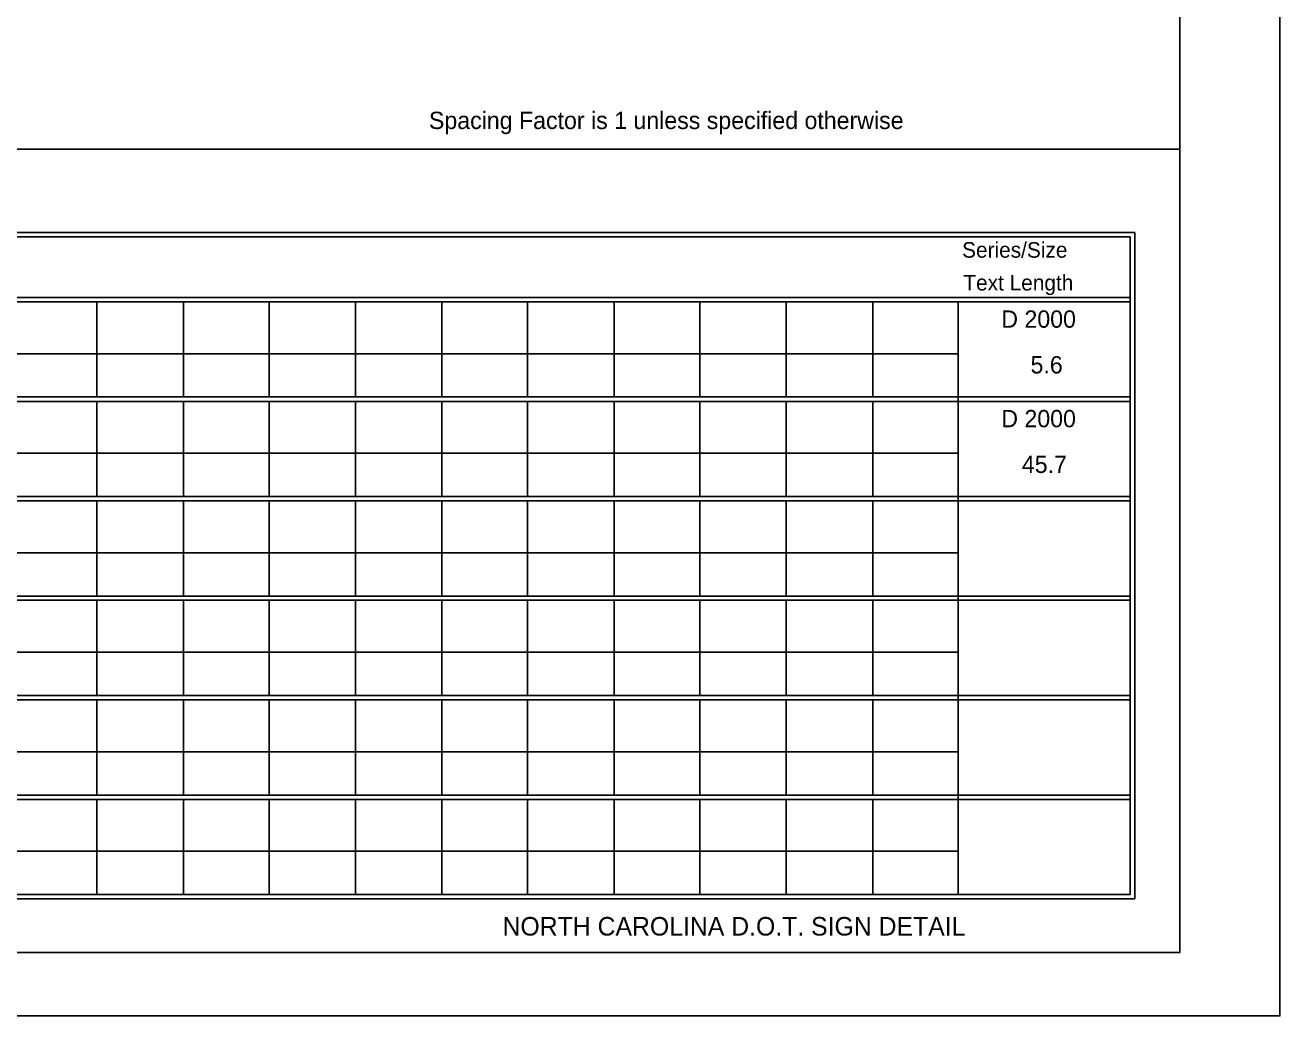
# Model space of a CAD drawing. Extents: x 1708.4 to 1771.6, y 238.3 to 283.4.
# Drawn here: x 1725.12 to 1738.44, y 238.25 to 248.77 of the extents above; entities that cross this region are included whole.
import ezdxf

# ---------------------------------------------------------------- set-up
doc = ezdxf.new("R2010")
doc.units = 0
doc.layers.add('Level 6', color=7, linetype='Continuous')
doc.layers.add('Level 9', color=7, linetype='Continuous')

msp = doc.modelspace()

# ---------------------------------------------------------------- linework, layer by layer
at = {"layer": 'Level 6'}
for p, q in [((1720.221, 247.448), (1737.376, 247.448)), ((1709.428, 245.876), (1731.195, 245.876)), ((1709.428, 245.83), (1731.195, 245.83)), ((1725.883, 245.83), (1725.883, 244.82)), ((1726.8, 245.83), (1726.8, 244.82)), ((1727.709, 245.83), (1727.709, 244.82)), ((1728.627, 245.83), (1728.627, 244.82)), ((1729.544, 245.83), (1729.544, 244.82)), ((1730.221, 245.876), (1736.849, 245.876)), ((1730.221, 245.83), (1736.849, 245.83)), ((1730.453, 245.83), (1730.453, 244.82)), ((1730.453, 245.83), (1730.453, 244.82)), ((1731.371, 245.83), (1731.371, 244.82)), ((1732.279, 245.83), (1732.279, 244.82)), ((1733.197, 245.83), (1733.197, 244.82)), ((1734.115, 245.83), (1734.115, 244.82)), ((1735.023, 245.83), (1735.023, 239.61)), ((1710.346, 245.279), (1731.195, 245.279)), ((1730.221, 245.279), (1735.023, 245.279)), ((1735.023, 245.07), (1735.023, 244.82)), ((1709.428, 244.82), (1731.195, 244.82)), ((1709.428, 244.774), (1731.195, 244.774)), ((1725.883, 244.774), (1725.883, 243.764)), ((1726.8, 244.774), (1726.8, 243.764)), ((1727.709, 244.774), (1727.709, 243.764)), ((1728.627, 244.774), (1728.627, 243.764)), ((1729.544, 244.774), (1729.544, 243.764)), ((1730.221, 244.82), (1736.849, 244.82)), ((1730.221, 244.774), (1736.849, 244.774)), ((1730.453, 244.774), (1730.453, 243.764)), ((1730.453, 244.774), (1730.453, 243.764)), ((1731.371, 244.774), (1731.371, 243.764)), ((1732.279, 244.774), (1732.279, 243.764)), ((1733.197, 244.774), (1733.197, 243.764)), ((1734.115, 244.774), (1734.115, 243.764)), ((1735.023, 244.774), (1735.023, 244.295)), ((1710.346, 244.223), (1731.195, 244.223)), ((1730.221, 244.223), (1735.023, 244.223)), ((1735.023, 244.093), (1735.023, 243.764)), ((1709.428, 243.764), (1731.195, 243.764)), ((1709.428, 243.718), (1731.195, 243.718)), ((1725.883, 243.718), (1725.883, 242.708)), ((1726.8, 243.718), (1726.8, 242.708)), ((1727.709, 243.718), (1727.709, 242.708)), ((1728.627, 243.718), (1728.627, 242.708)), ((1729.544, 243.718), (1729.544, 242.708)), ((1730.221, 243.764), (1736.849, 243.764)), ((1730.221, 243.718), (1736.849, 243.718)), ((1730.453, 243.718), (1730.453, 242.708)), ((1730.453, 243.718), (1730.453, 242.708)), ((1731.371, 243.718), (1731.371, 242.708)), ((1732.279, 243.718), (1732.279, 242.708)), ((1733.197, 243.718), (1733.197, 242.708)), ((1734.115, 243.718), (1734.115, 242.708)), ((1735.023, 243.718), (1735.023, 243.308)), ((1710.346, 243.168), (1731.195, 243.168)), ((1730.221, 243.168), (1735.023, 243.168)), ((1735.023, 243.006), (1735.023, 242.708)), ((1709.428, 242.708), (1731.195, 242.708)), ((1709.428, 242.663), (1731.195, 242.663)), ((1725.883, 242.663), (1725.883, 241.653)), ((1726.8, 242.663), (1726.8, 241.653)), ((1727.709, 242.663), (1727.709, 241.653)), ((1728.627, 242.663), (1728.627, 241.653)), ((1729.544, 242.663), (1729.544, 241.653)), ((1730.221, 242.708), (1736.849, 242.708)), ((1730.221, 242.663), (1736.849, 242.663)), ((1730.453, 242.663), (1730.453, 241.653)), ((1730.453, 242.663), (1730.453, 241.653)), ((1731.371, 242.663), (1731.371, 241.653)), ((1732.279, 242.663), (1732.279, 241.653)), ((1733.197, 242.663), (1733.197, 241.653)), ((1734.115, 242.663), (1734.115, 241.653)), ((1735.023, 242.663), (1735.023, 242.22)), ((1710.346, 242.112), (1731.195, 242.112)), ((1730.221, 242.112), (1735.023, 242.112)), ((1735.023, 241.918), (1735.023, 241.653)), ((1725.883, 241.77), (1725.883, 241.653)), ((1726.8, 241.77), (1726.8, 241.653)), ((1727.709, 241.77), (1727.709, 241.653)), ((1728.627, 241.77), (1728.627, 241.653)), ((1729.544, 241.77), (1729.544, 241.653)), ((1730.453, 241.77), (1730.453, 241.653)), ((1730.453, 241.77), (1730.453, 241.653)), ((1731.371, 241.77), (1731.371, 241.653)), ((1732.279, 241.77), (1732.279, 241.653)), ((1733.197, 241.77), (1733.197, 241.653)), ((1734.115, 241.77), (1734.115, 241.653)), ((1735.023, 241.77), (1735.023, 241.653)), ((1709.428, 241.653), (1731.195, 241.653)), ((1709.428, 241.653), (1731.195, 241.653)), ((1709.428, 241.607), (1731.195, 241.607)), ((1709.428, 241.607), (1731.195, 241.607)), ((1725.883, 241.607), (1725.883, 240.663)), ((1725.883, 241.607), (1725.883, 240.597)), ((1726.8, 241.607), (1726.8, 240.663)), ((1726.8, 241.607), (1726.8, 240.597)), ((1727.709, 241.607), (1727.709, 240.663)), ((1727.709, 241.607), (1727.709, 240.597)), ((1728.627, 241.607), (1728.627, 240.663)), ((1728.627, 241.607), (1728.627, 240.597)), ((1729.544, 241.607), (1729.544, 240.663)), ((1729.544, 241.607), (1729.544, 240.597)), ((1730.221, 241.653), (1736.849, 241.653)), ((1730.221, 241.653), (1736.849, 241.653)), ((1730.221, 241.607), (1736.849, 241.607)), ((1730.221, 241.607), (1736.849, 241.607)), ((1730.453, 241.607), (1730.453, 240.663)), ((1730.453, 241.607), (1730.453, 240.597)), ((1730.453, 241.607), (1730.453, 240.663)), ((1730.453, 241.607), (1730.453, 240.597)), ((1731.371, 241.607), (1731.371, 240.663)), ((1731.371, 241.607), (1731.371, 240.597)), ((1732.279, 241.607), (1732.279, 240.663)), ((1732.279, 241.607), (1732.279, 240.597)), ((1733.197, 241.607), (1733.197, 240.663)), ((1733.197, 241.607), (1733.197, 240.597)), ((1734.115, 241.607), (1734.115, 240.663)), ((1734.115, 241.607), (1734.115, 240.597)), ((1735.023, 241.607), (1735.023, 241.152)), ((1735.023, 241.607), (1735.023, 241.152)), ((1710.346, 241.056), (1731.195, 241.056)), ((1710.346, 241.056), (1731.195, 241.056)), ((1730.221, 241.056), (1735.023, 241.056)), ((1730.221, 241.056), (1734.785, 241.056)), ((1735.023, 240.89), (1735.023, 240.663)), ((1735.023, 240.89), (1735.023, 240.597)), ((1725.883, 240.714), (1725.883, 240.597)), ((1726.8, 240.714), (1726.8, 240.597)), ((1727.709, 240.714), (1727.709, 240.597)), ((1728.627, 240.714), (1728.627, 240.597)), ((1729.544, 240.714), (1729.544, 240.597)), ((1730.453, 240.714), (1730.453, 240.597)), ((1730.453, 240.714), (1730.453, 240.597)), ((1731.371, 240.714), (1731.371, 240.597)), ((1732.279, 240.714), (1732.279, 240.597)), ((1733.197, 240.714), (1733.197, 240.597)), ((1734.115, 240.714), (1734.115, 240.597)), ((1735.023, 240.714), (1735.023, 240.597)), ((1709.428, 240.597), (1731.195, 240.597)), ((1709.428, 240.597), (1731.195, 240.597)), ((1709.428, 240.551), (1731.195, 240.551)), ((1709.428, 240.551), (1731.195, 240.551)), ((1725.883, 240.551), (1725.883, 239.541)), ((1725.883, 240.551), (1725.883, 239.541)), ((1726.8, 240.551), (1726.8, 239.541)), ((1726.8, 240.551), (1726.8, 239.541)), ((1727.709, 240.551), (1727.709, 239.541)), ((1727.709, 240.551), (1727.709, 239.541)), ((1728.627, 240.551), (1728.627, 239.541)), ((1728.627, 240.551), (1728.627, 239.541)), ((1729.544, 240.551), (1729.544, 239.541)), ((1729.544, 240.551), (1729.544, 239.541)), ((1730.221, 240.597), (1736.849, 240.597)), ((1730.221, 240.597), (1736.849, 240.597)), ((1730.221, 240.551), (1736.849, 240.551)), ((1730.221, 240.551), (1736.849, 240.551)), ((1730.453, 240.551), (1730.453, 239.541)), ((1730.453, 240.551), (1730.453, 239.541)), ((1730.453, 240.551), (1730.453, 239.541)), ((1730.453, 240.551), (1730.453, 239.541)), ((1731.371, 240.551), (1731.371, 239.541)), ((1731.371, 240.551), (1731.371, 239.541)), ((1732.279, 240.551), (1732.279, 239.541)), ((1732.279, 240.551), (1732.279, 239.541)), ((1733.197, 240.551), (1733.197, 239.541)), ((1733.197, 240.551), (1733.197, 239.541)), ((1734.115, 240.551), (1734.115, 239.541)), ((1734.115, 240.551), (1734.115, 239.541)), ((1735.023, 240.551), (1735.023, 240.126)), ((1735.023, 240.551), (1735.023, 240.126)), ((1710.346, 240), (1731.195, 240)), ((1710.346, 240), (1731.195, 240)), ((1730.221, 240), (1735.023, 240)), ((1730.221, 240), (1734.847, 240)), ((1735.023, 239.803), (1735.023, 239.541)), ((1735.023, 239.803), (1735.023, 239.541)), ((1709.381, 239.495), (1731.195, 239.495)), ((1709.428, 239.541), (1731.195, 239.541)), ((1709.428, 239.541), (1731.195, 239.541)), ((1709.428, 239.495), (1731.195, 239.495)), ((1730.221, 239.541), (1736.849, 239.541)), ((1730.221, 239.541), (1736.849, 239.541)), ((1730.221, 239.495), (1736.896, 239.495)), ((1730.221, 239.495), (1736.849, 239.495))]:
    msp.add_line(p, q, dxfattribs=at)
msp.add_lwpolyline([(1709.065, 258.583), (1737.376, 258.583), (1737.376, 238.927), (1709.065, 238.927)], close=True, dxfattribs=at)
for points in [[(1709.381, 240.663), (1709.381, 246.565), (1731.195, 246.565)], [(1709.428, 240.663), (1709.428, 246.519), (1731.195, 246.519)], [(1730.221, 246.565), (1736.896, 246.565), (1736.896, 240.663)], [(1730.221, 246.519), (1736.849, 246.519), (1736.849, 240.663)], [(1736.849, 241.77), (1736.849, 239.541)], [(1736.896, 241.77), (1736.896, 239.495)]]:
    msp.add_lwpolyline(points, dxfattribs=at)
at = {"layer": 'Level 9'}
msp.add_lwpolyline([(1708.374, 238.254), (1738.436, 238.254), (1738.436, 259.278), (1708.374, 259.278)], close=True, dxfattribs=at)

# ---------------------------------------------------------------- texts
at = {"layer": 'Level 6'}
for s, height, p in [('Spacing Factor is 1 unless specified otherwise', 0.18363, (1729.406, 247.663)), ('Series/Size', 0.16527, (1735.064, 246.298)), ('Text Length', 0.16527, (1735.077, 245.95)), ('NORTH CAROLINA D.O.T. SIGN DETAIL', 0.19675, (1730.187, 239.106))]:
    msp.add_text(s, height=height, rotation=360, dxfattribs=at).set_placement(p)
for s, p in [('D 2000', (1735.48, 245.555)), ('5.6', (1735.79, 245.07)), ('D 2000', (1735.48, 244.499)), ('45.7', (1735.698, 244.014))]:
    msp.add_text(s, height=0.1836, dxfattribs=at).set_placement(p)

doc.saveas('drawing.dxf')
